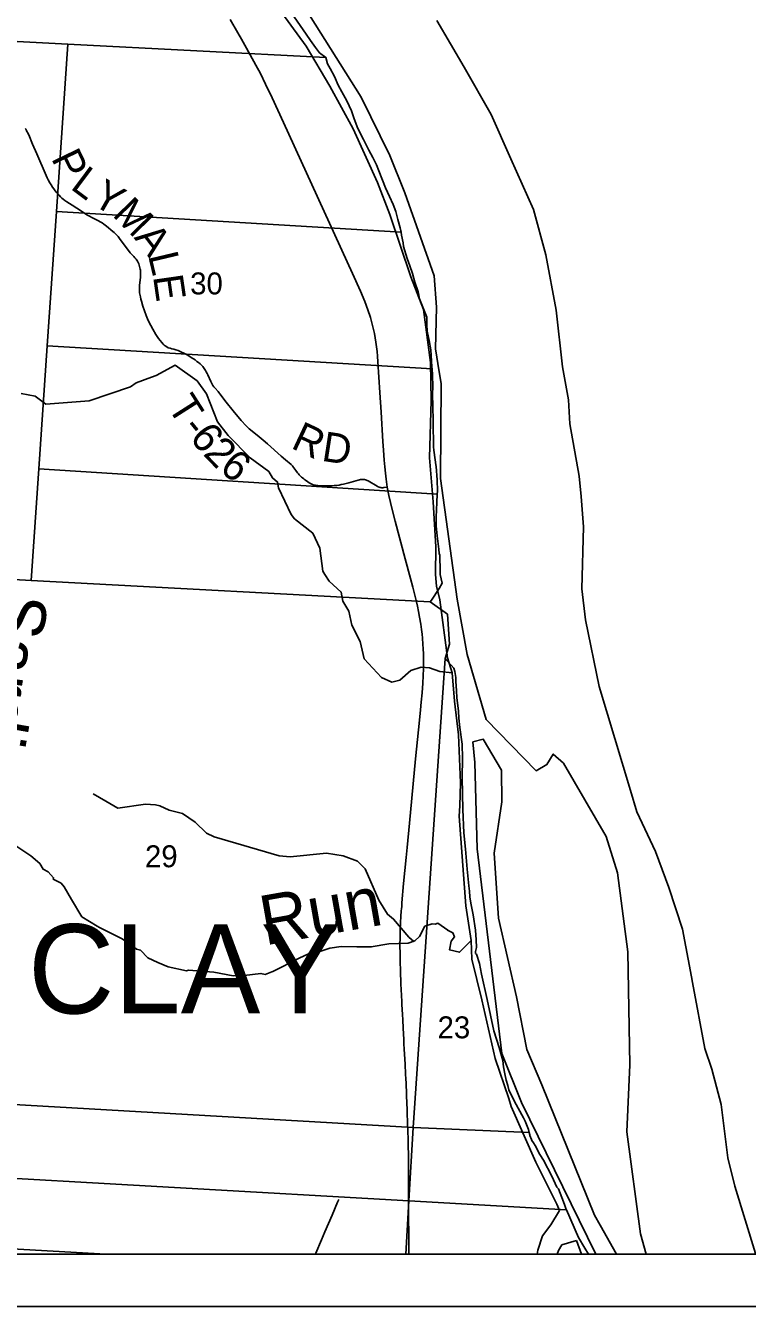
# Model space of a CAD drawing. Extents: x 21.4 to 65.3, y 4 to 26.
# Drawn here: x 27.53 to 28.907, y 17.954 to 20.4 of the extents above; entities that cross this region are included whole.
import ezdxf

# ---------------------------------------------------------------- set-up
doc = ezdxf.new("R2010")
doc.units = 0
for name, color, linetype in [('Default', 7, 'Continuous'), ('GM_X_Major_River', 7, 'Continuous'), ('GM_X_Minor_River', 7, 'Continuous'), ('GM_X_Minor_River_Text', 7, 'Continuous'), ('GM_X_Section', 7, 'Continuous'), ('GM_X_Section_Text', 7, 'Continuous'), ('GM_X_State_Route', 7, 'Continuous'), ('GM_X_Township_Road', 7, 'Continuous'), ('GM_X_Township_Road_Text', 7, 'Continuous'), ('GM_X_Township_Text', 7, 'Continuous'), ('SH_Cut_Line', 7, 'Continuous'), ('SH_Data', 7, 'Continuous')]:
    doc.layers.add(name, color=color, linetype=linetype)

msp = doc.modelspace()

# ---------------------------------------------------------------- linework, layer by layer
at = {"layer": 'Default'}
msp.add_lwpolyline([(25.1151, 18.0542), (28.6177, 18.0542), (28.4756, 18.3435), (28.4382, 18.4371), (28.3913, 18.8283), (28.3871, 18.9932), (28.383, 19.0322), (28.403, 19.0375), (28.4378, 18.9784), (28.4382, 18.9181), (28.4238, 18.8196), (28.4321, 18.6956), (28.4665, 18.5455), (28.4862, 18.4451), (28.5145, 18.3773), (28.615, 18.1282), (28.626, 18.1093), (28.6572, 18.0542), (28.7135, 18.0542), (28.7031, 18.0926), (28.6766, 18.2878), (28.6823, 18.4156), (28.6789, 18.6316), (28.6593, 18.7821), (28.6373, 18.8514), (28.5557, 18.992), (28.5364, 19.0091), (28.5243, 18.989), (28.5036, 18.9773), (28.4087, 19.075), (28.372, 19.1994), (28.3531, 19.3047), (28.3214, 19.5352), (28.3225, 19.7171), (28.3188, 19.7391), (28.312, 19.7834), (28.3135, 19.8626), (28.309, 19.9226), (28.2534, 20.0809), (28.2243, 20.1526), (28.1702, 20.2638), (28.0527, 20.4505)], dxfattribs=at)
for points in [[(27.6828, 18.0542), (28.255, 18.0542), (28.2609, 18.1555), (27.3661, 18.2064), (27.3583, 18.0722)], [(28.255, 18.0542), (28.6038, 18.0542), (28.5966, 18.0656), (28.5848, 18.0857), (28.562, 18.1384), (28.2609, 18.1555)], [(27.3572, 18.0542), (27.6828, 18.0542), (27.3583, 18.0722)]]:
    msp.add_lwpolyline(points, close=True, dxfattribs=at)
at = {"layer": 'GM_X_Major_River'}
msp.add_line((28.5806, 18.0797), (28.5903, 18.0542), dxfattribs=at)
for points in [[(27.9894, 20.4659), (28.0651, 20.3615), (28.1104, 20.2846), (28.1549, 20.2032), (28.2011, 20.1005), (28.2244, 20.0398), (28.2645, 19.9206), (28.2888, 19.8579)], [(28.5418, 19.8568), (28.5222, 19.9629), (28.4988, 20.0493), (28.4553, 20.1463), (28.4179, 20.2304), (28.3665, 20.3213), (28.3144, 20.4103)], [(28.2888, 19.8579), (28.3022, 19.7567), (28.3034, 19.6842), (28.3002, 19.5746), (28.3071, 19.4908), (28.3124, 19.4047), (28.312, 19.352), (28.3136, 19.33), (28.3198, 19.3038), (28.3344, 19.1931), (28.3436, 19.164), (28.3477, 19.1101), (28.3556, 19.0461), (28.3595, 18.9543), (28.3579, 18.9099), (28.3572, 18.8902), (28.3699, 18.7195), (28.3801, 18.6528), (28.3814, 18.6175), (28.4003, 18.5395), (28.4259, 18.4278), (28.4517, 18.3513), (28.4559, 18.3357), (28.5034, 18.2298), (28.5435, 18.1496), (28.5485, 18.1375)], [(28.9229, 18.0542), (28.9225, 18.0552), (28.8829, 18.1839), (28.8697, 18.2381), (28.8567, 18.3397), (28.8393, 18.4071), (28.8255, 18.4465), (28.8025, 18.5727), (28.8002, 18.5833), (28.7834, 18.6746), (28.7573, 18.7545), (28.7316, 18.823), (28.696, 18.899), (28.6837, 18.9396), (28.624, 19.1384), (28.5983, 19.2653), (28.5912, 19.3244), (28.594, 19.4432), (28.5899, 19.5008), (28.5859, 19.5399), (28.5683, 19.6396), (28.5654, 19.6858), (28.5541, 19.7487), (28.5418, 19.8568)], [(28.5485, 18.1375), (28.532, 18.1097), (28.5159, 18.0888), (28.5073, 18.0618), (28.5058, 18.0542)], [(28.5439, 18.0542), (28.5463, 18.0609), (28.553, 18.0715), (28.5806, 18.0797)]]:
    msp.add_lwpolyline(points, dxfattribs=at)
at = {"layer": 'GM_X_Minor_River'}
for points in [[(28.3436, 19.164), (28.3203, 19.1666), (28.3001, 19.1741), (28.2847, 19.175), (28.2648, 19.1688), (28.2435, 19.1501), (28.2286, 19.1467), (28.2085, 19.1554), (28.1756, 19.191), (28.1679, 19.2239), (28.1522, 19.2555), (28.1462, 19.2819), (28.135, 19.3009), (28.1318, 19.3184), (28.1086, 19.3393), (28.1007, 19.3521), (28.0967, 19.3583), (28.0913, 19.4025), (28.0777, 19.4307), (28.0427, 19.4587), (28.0365, 19.4669), (28.0123, 19.5174), (28.0104, 19.5285), (28.0008, 19.5364), (27.9936, 19.5488), (27.9581, 19.575), (27.916, 19.6177), (27.8956, 19.6438), (27.8749, 19.6969), (27.8568, 19.7221), (27.8149, 19.7516), (27.7785, 19.7322), (27.77, 19.7287), (27.7406, 19.7179), (27.7294, 19.7106), (27.6511, 19.6835), (27.5681, 19.6771), (27.5478, 19.6925), (27.5211, 19.6979)], [(28.2701, 18.6514), (28.2607, 18.6596), (28.2319, 18.694), (28.2201, 18.7031), (28.2039, 18.7302), (28.1774, 18.7899), (28.1631, 18.8048), (28.1358, 18.8148), (28.1038, 18.8196), (28.0341, 18.8131), (28.0137, 18.8145), (27.8893, 18.8511), (27.8748, 18.858), (27.8531, 18.8788), (27.8291, 18.8956), (27.8032, 18.9021), (27.7857, 18.9099), (27.7774, 18.912), (27.7582, 18.9134), (27.7054, 18.906), (27.6824, 18.9189), (27.6586, 18.9333)], [(28.2942, 18.6811), (28.2911, 18.6801), (28.2809, 18.6607), (28.2722, 18.6523), (28.2594, 18.6481), (28.2227, 18.6469), (28.1891, 18.6407), (28.1619, 18.641), (28.132, 18.6417), (28.1101, 18.6386), (28.0731, 18.6264), (28.0697, 18.6275), (28.0515, 18.6195), (28.0016, 18.5939), (27.9994, 18.5931), (27.9865, 18.5881), (27.9786, 18.59), (27.9465, 18.5861), (27.9257, 18.5857), (27.8886, 18.5925), (27.8402, 18.5965), (27.8368, 18.595), (27.8017, 18.6025), (27.782, 18.6108), (27.7631, 18.6199), (27.7491, 18.6343), (27.7412, 18.6362), (27.7332, 18.6434), (27.7128, 18.6571), (27.6704, 18.6779), (27.6663, 18.6805), (27.6368, 18.6983), (27.6171, 18.7313), (27.6034, 18.7556), (27.5974, 18.7625), (27.5823, 18.7704), (27.583, 18.7727), (27.5724, 18.7841), (27.5633, 18.789), (27.5569, 18.8), (27.5395, 18.8144), (27.5092, 18.8348)], [(28.2933, 18.6808), (28.3051, 18.6846)], [(28.3351, 18.6727), (28.3164, 18.6862), (28.3108, 18.6839), (28.3051, 18.6846)], [(28.3801, 18.6528), (28.3577, 18.6305), (28.3384, 18.6353), (28.3414, 18.6517), (28.3478, 18.6597), (28.3448, 18.6677), (28.3349, 18.6728)]]:
    msp.add_lwpolyline(points, dxfattribs=at)
at = {"layer": 'GM_X_Section'}
for points in [[(27.3731, 20.4834), (28.0222, 20.4469), (28.0334, 20.4311), (28.0422, 20.4171), (28.0647, 20.3839), (28.073, 20.3722), (28.0829, 20.3589), (28.0906, 20.3484), (28.1023, 20.3397), (27.6101, 20.3651), (27.367, 20.3777)], [(27.367, 20.3777), (27.6101, 20.3651), (27.5883, 20.0453), (27.5709, 19.7889), (27.5549, 19.5538), (27.5403, 19.3404), (27.3079, 19.3538), (27.3231, 19.6175), (27.3378, 19.8728), (27.3527, 20.1302)], [(27.6101, 20.3651), (28.1023, 20.3397), (28.1058, 20.3272), (28.1107, 20.3185), (28.1187, 20.303), (28.126, 20.2867), (28.1333, 20.2742), (28.1424, 20.2568), (28.1512, 20.2376), (28.1565, 20.2224), (28.1638, 20.2039), (28.1741, 20.1831), (28.1848, 20.1627), (28.1924, 20.1487), (28.1993, 20.1347), (28.2035, 20.1233), (28.2161, 20.0908), (28.2237, 20.0741), (28.231, 20.0586), (28.236, 20.0454), (28.2398, 20.0302), (28.2444, 20.014), (28.246, 20.0061), (27.5883, 20.0453)], [(28.246, 20.0061), (28.2471, 20.0003), (28.2502, 19.9856), (28.251, 19.9784), (28.2575, 19.9557), (28.2625, 19.9417), (28.2678, 19.9269), (28.272, 19.9106), (28.2789, 19.8921), (28.2813, 19.8788), (28.2949, 19.8438), (28.2953, 19.8283), (28.2961, 19.8173), (28.2965, 19.8139), (28.2999, 19.7991), (28.303, 19.7814), (28.305, 19.7484), (28.3052, 19.7447), (27.5709, 19.7889), (27.5883, 20.0453)], [(27.5709, 19.7889), (28.3052, 19.7447), (28.3059, 19.7329), (28.3067, 19.7109), (28.306, 19.6957), (28.306, 19.6885), (28.3064, 19.6821), (28.3073, 19.6374), (28.3078, 19.6018), (28.3079, 19.5957), (28.3086, 19.5893), (28.311, 19.5711), (28.3125, 19.5613), (28.3133, 19.5582), (28.3149, 19.5328), (28.3153, 19.5112), (28.3151, 19.5052), (27.5549, 19.5538)], [(28.3151, 19.5052), (28.3143, 19.4893), (28.3129, 19.4616), (28.3129, 19.4453), (28.3149, 19.4256), (28.318, 19.4006), (28.3188, 19.3919), (28.3199, 19.3893), (28.3208, 19.3578), (28.3208, 19.3521), (28.3247, 19.3355), (28.3186, 19.3256), (28.3039, 19.3032), (28.3017, 19.2998), (27.5403, 19.3404), (27.5549, 19.5538)], [(27.5403, 19.3404), (28.3017, 19.2998), (28.3345, 19.2762), (28.3347, 19.276), (28.3387, 19.2192), (28.3305, 19.1915), (28.269, 18.2956), (27.3744, 18.3474), (27.2401, 18.3567), (27.2592, 18.6074), (27.2763, 18.86), (27.2925, 19.1065), (27.3079, 19.3538)], [(28.269, 18.2956), (28.3305, 19.1915), (28.3465, 19.173), (28.3484, 19.1666), (28.3491, 19.1628), (28.3507, 19.1552), (28.3503, 19.148), (28.3519, 19.1306), (28.3527, 19.1166), (28.3539, 19.1071), (28.3555, 19.0912), (28.3563, 19.0779), (28.3582, 19.0601), (28.3625, 19.0279), (28.363, 19.0014), (28.3627, 18.9639), (28.3637, 18.9033), (28.3661, 18.8586), (28.3693, 18.8275), (28.3724, 18.7893), (28.3756, 18.7575), (28.3764, 18.7472), (28.3772, 18.7362), (28.3791, 18.7245), (28.3834, 18.7018), (28.388, 18.6726), (28.3896, 18.6545), (28.39, 18.6397), (28.3878, 18.6321), (28.3878, 18.6306), (28.3882, 18.6283), (28.3897, 18.6268), (28.3954, 18.609), (28.3997, 18.5886), (28.4104, 18.5405), (28.4231, 18.4807), (28.4331, 18.4485), (28.4377, 18.4326), (28.44, 18.4235), (28.4416, 18.4114), (28.4439, 18.3985), (28.4466, 18.3864), (28.4497, 18.3758), (28.452, 18.3675), (28.4619, 18.3467), (28.4695, 18.3327), (28.4794, 18.3141), (28.4829, 18.3077), (28.4894, 18.2922), (28.4908, 18.2861)], [(27.3744, 18.3474), (28.269, 18.2956), (28.2609, 18.1555), (27.3661, 18.2064)], [(28.269, 18.2956), (28.4908, 18.2861), (28.4917, 18.282), (28.492, 18.2805), (28.4947, 18.2729), (28.4957, 18.2713), (28.4985, 18.2668), (28.502, 18.2612), (28.5111, 18.2445), (28.518, 18.2332), (28.5336, 18.2026), (28.5435, 18.1821), (28.5447, 18.1806), (28.5462, 18.1784), (28.5561, 18.1541), (28.5584, 18.1469), (28.5607, 18.1413), (28.562, 18.1384), (28.2609, 18.1555)]]:
    msp.add_lwpolyline(points, close=True, dxfattribs=at)
at = {"layer": 'GM_X_State_Route'}
msp.add_lwpolyline([(28.2611, 18.0542), (28.261, 18.0578), (28.2609, 18.0677), (28.2608, 18.0914), (28.2604, 18.1237), (28.2604, 18.152), (28.2603, 18.174), (28.2603, 18.2005), (28.26, 18.2298), (28.2596, 18.2746), (28.2592, 18.2876), (28.2578, 18.3235), (28.2574, 18.3335), (28.2572, 18.3394), (28.2556, 18.3807), (28.2552, 18.3885), (28.2547, 18.3974), (28.2536, 18.4166), (28.252, 18.4457), (28.2516, 18.4559), (28.2512, 18.4642), (28.25, 18.4853), (28.2492, 18.5014), (28.2486, 18.5119), (28.2476, 18.5306), (28.2474, 18.5368), (28.2463, 18.5591), (28.2458, 18.5696), (28.2447, 18.5957), (28.2443, 18.6125), (28.2442, 18.6182), (28.2441, 18.6237), (28.2441, 18.633), (28.244, 18.6379), (28.244, 18.6439), (28.244, 18.6479), (28.2441, 18.6547), (28.2441, 18.659), (28.2442, 18.6621), (28.2443, 18.6681), (28.2445, 18.6746), (28.2446, 18.6789), (28.2447, 18.6808), (28.2448, 18.6833), (28.2449, 18.6858), (28.2451, 18.6907), (28.2454, 18.6956), (28.2457, 18.7005), (28.2459, 18.7029), (28.2461, 18.706), (28.2465, 18.7101), (28.2467, 18.7131), (28.2473, 18.7188), (28.2478, 18.7248), (28.2508, 18.762), (28.2558, 18.8114), (28.2577, 18.8306), (28.262, 18.877), (28.2739, 19.0002), (28.2813, 19.0736), (28.283, 19.0934), (28.2846, 19.1082), (28.2863, 19.1262), (28.2876, 19.1447), (28.2882, 19.1582), (28.2888, 19.1726), (28.2889, 19.1887), (28.2887, 19.2005), (28.2882, 19.2098), (28.2877, 19.2191), (28.2868, 19.2306), (28.2862, 19.2382), (28.2851, 19.2471), (28.2838, 19.2573), (28.2814, 19.2705), (28.2795, 19.2811), (28.2773, 19.2914), (28.2749, 19.3023), (28.2717, 19.3152), (28.2687, 19.3276), (28.2642, 19.3443), (28.2541, 19.3823), (28.2345, 19.4542), (28.2282, 19.4789), (28.2258, 19.4896), (28.2227, 19.5032), (28.2197, 19.5189), (28.2175, 19.5339), (28.2161, 19.5453), (28.2148, 19.5577), (28.2138, 19.5707), (28.2125, 19.5896), (28.2115, 19.6059), (28.208, 19.6622), (28.2056, 19.7), (28.202, 19.7583), (28.2011, 19.769), (28.2003, 19.7781), (28.198, 19.7959), (28.1951, 19.8124), (28.1918, 19.8275), (28.1875, 19.8431), (28.1828, 19.8578), (28.1769, 19.8735), (28.1686, 19.8935), (28.1535, 19.9269), (28.0214, 20.2156), (27.9999, 20.2625), (27.9872, 20.2888), (27.9776, 20.3088), (27.9687, 20.3246), (27.951, 20.3575), (27.9415, 20.3744), (27.9346, 20.3867), (27.9197, 20.4118)], dxfattribs=at)
at = {"layer": 'GM_X_Township_Road'}
for points in [[(27.5285, 20.2041), (27.5297, 20.2024), (27.5311, 20.2002), (27.5322, 20.1982), (27.5335, 20.1958), (27.5345, 20.1938), (27.5355, 20.1916), (27.543, 20.1742), (27.551, 20.1558), (27.5688, 20.114), (27.5707, 20.11), (27.5729, 20.1056), (27.5759, 20.1002), (27.5782, 20.0962), (27.5809, 20.0918), (27.5832, 20.0887), (27.5861, 20.0849), (27.5894, 20.081), (27.5934, 20.0764), (27.5961, 20.0737), (27.5987, 20.0711), (27.6014, 20.0688), (27.6045, 20.0663), (27.6081, 20.0638), (27.6182, 20.0574), (27.6359, 20.0459), (27.6464, 20.0393), (27.6514, 20.0365), (27.6562, 20.0338), (27.6688, 20.0276), (27.6719, 20.0258), (27.6754, 20.0237), (27.6787, 20.0215), (27.6814, 20.0194), (27.6839, 20.0174), (27.6961, 20.0074), (27.6987, 20.0051), (27.7012, 20.0026), (27.7035, 20.0003), (27.7059, 19.9974), (27.7085, 19.9941), (27.729, 19.9666), (27.7342, 19.9611), (27.7362, 19.9592), (27.7383, 19.957), (27.7403, 19.9545), (27.7417, 19.9526), (27.7431, 19.9503), (27.7442, 19.9481), (27.7453, 19.9454), (27.7463, 19.9426), (27.747, 19.9402), (27.7477, 19.9378), (27.7481, 19.9354), (27.7485, 19.9332), (27.7487, 19.9306), (27.7489, 19.9282), (27.7489, 19.9257), (27.7489, 19.9229), (27.7486, 19.9195), (27.7469, 19.9045), (27.7467, 19.9022), (27.7467, 19.8996), (27.7467, 19.8972), (27.7468, 19.8951), (27.7469, 19.8929), (27.7472, 19.8901), (27.7475, 19.8875), (27.748, 19.8848), (27.7485, 19.8821), (27.7496, 19.878), (27.7506, 19.874), (27.7533, 19.8648), (27.7593, 19.847), (27.7621, 19.8403), (27.7652, 19.8333), (27.7683, 19.8275), (27.7722, 19.8205), (27.7779, 19.8105), (27.7805, 19.8066), (27.7831, 19.803), (27.7861, 19.7991), (27.7896, 19.7949), (27.7923, 19.7918), (27.7941, 19.7901), (27.796, 19.7886), (27.7988, 19.7867), (27.8016, 19.7852), (27.8051, 19.7841), (27.8084, 19.7832), (27.8124, 19.7823), (27.8163, 19.7811), (27.8208, 19.7797), (27.826, 19.7776), (27.8326, 19.7744), (27.8391, 19.7707), (27.8453, 19.7668), (27.8529, 19.7618), (27.8565, 19.7591), (27.8596, 19.7567), (27.8625, 19.7544), (27.8648, 19.7523), (27.8665, 19.7507), (27.8679, 19.7491), (27.8692, 19.7476), (27.8704, 19.7458), (27.8716, 19.7439), (27.8728, 19.7418), (27.8742, 19.7393), (27.8758, 19.7362), (27.8772, 19.7333), (27.8831, 19.7205), (27.885, 19.7169), (27.8871, 19.7133), (27.889, 19.7107), (27.8914, 19.7079), (27.8969, 19.7018), (27.8986, 19.6995), (27.9004, 19.6971), (27.9124, 19.6814), (27.9258, 19.6646), (27.941, 19.6461), (27.9504, 19.6362), (27.9531, 19.6335), (27.956, 19.6306), (27.9589, 19.6281), (27.9627, 19.625), (27.9712, 19.6185), (27.983, 19.6085), (27.991, 19.6014), (28.0171, 19.5778), (28.0253, 19.571), (28.036, 19.562), (28.0373, 19.5611), (28.0381, 19.5604), (28.0388, 19.5596), (28.0398, 19.5583), (28.0452, 19.5505), (28.0487, 19.546), (28.0502, 19.5442), (28.0518, 19.5424), (28.0538, 19.5403), (28.056, 19.5382), (28.058, 19.5364), (28.0602, 19.5346), (28.0624, 19.533), (28.0654, 19.5309), (28.0684, 19.5289), (28.0709, 19.5272), (28.0733, 19.5257), (28.0755, 19.5245), (28.0773, 19.5237), (28.0795, 19.5229), (28.0819, 19.5224), (28.0843, 19.5221), (28.0872, 19.5218), (28.0907, 19.5216), (28.0944, 19.5214), (28.0984, 19.5212), (28.113, 19.5215), (28.1185, 19.5219), (28.1233, 19.5223), (28.1277, 19.523), (28.132, 19.5237), (28.1364, 19.5246), (28.1411, 19.5257), (28.1463, 19.527), (28.164, 19.5322), (28.1666, 19.5328), (28.1685, 19.5332), (28.1704, 19.5335), (28.1723, 19.5336), (28.1742, 19.5336), (28.1762, 19.5334), (28.1783, 19.5329), (28.1799, 19.5323), (28.1814, 19.5317), (28.183, 19.5309), (28.2006, 19.5207), (28.2024, 19.5198), (28.2041, 19.519), (28.2059, 19.5184), (28.2075, 19.5181), (28.2092, 19.5179), (28.2111, 19.5178), (28.2133, 19.518), (28.2197, 19.5189)], [(28.1272, 18.1581), (28.125, 18.153), (28.1144, 18.1281), (28.1005, 18.0966), (28.094, 18.0812), (28.0832, 18.0556), (28.0826, 18.0542)]]:
    msp.add_lwpolyline(points, dxfattribs=at)
at = {"layer": 'SH_Cut_Line'}
msp.add_lwpolyline([(23.5473, 18.0542), (28.6177, 18.0542), (28.4756, 18.3435), (28.4382, 18.4371), (28.3913, 18.8283), (28.3871, 18.9932), (28.383, 19.0322), (28.403, 19.0375), (28.4378, 18.9784), (28.4382, 18.9181), (28.4238, 18.8196), (28.4321, 18.6956), (28.4665, 18.5455), (28.4862, 18.4451), (28.5145, 18.3773), (28.615, 18.1282), (28.626, 18.1093), (28.6572, 18.0542), (28.7135, 18.0542), (28.7031, 18.0926), (28.6766, 18.2878), (28.6823, 18.4156), (28.6789, 18.6316), (28.6593, 18.7821), (28.6373, 18.8514), (28.5557, 18.992), (28.5364, 19.0091), (28.5243, 18.989), (28.5036, 18.9773), (28.4087, 19.075), (28.372, 19.1994), (28.3531, 19.3047), (28.3214, 19.5352), (28.3225, 19.7171), (28.3188, 19.7391), (28.312, 19.7834), (28.3135, 19.8626), (28.309, 19.9226), (28.2534, 20.0809), (28.2243, 20.1526), (28.1702, 20.2638), (28.0527, 20.4505)], dxfattribs=at)
at = {"layer": 'SH_Data'}
for p, q in [((23.5473, 18.0542), (30.3473, 18.0542)), ((23.4473, 17.9542), (30.4473, 17.9542))]:
    msp.add_line(p, q, dxfattribs=at)

# ---------------------------------------------------------------- texts
at = {"layer": 'GM_X_Minor_River_Text'}
for s, height, rotation, p in [('Sardis', 0.0947, 259.9987, (27.4813, 19.3234)), ('Run', 0.09469, 10.0015, (27.9859, 18.6433))]:
    msp.add_text(s, height=height, rotation=rotation, dxfattribs=at).set_placement(p)
at = {"layer": 'GM_X_Section_Text'}
for s, p in [('30', (27.8436, 19.8871)), ('29', (27.7574, 18.7929)), ('23', (28.3157, 18.4662))]:
    msp.add_text(s, height=0.04186, rotation=0, dxfattribs=at).set_placement(p)
at = {"layer": 'GM_X_Township_Road_Text'}
for s, rotation, p in [('P', 295.7406, (27.5777, 20.1472)), ('L', 323.2377, (27.6131, 20.09)), ('Y', 330.0747, (27.6533, 20.0605)), ('M', 314.386, (27.6934, 20.038)), ('A', 307.4309, (27.7353, 19.9953)), ('L', 283.3986, (27.7631, 19.9613)), ('E', 278.2483, (27.7726, 19.9213)), ('T', 302.5192, (27.7991, 19.6727)), ('-', 309.2461, (27.8262, 19.6309)), ('6', 308.9817, (27.841, 19.6129)), ('R', 334.8856, (28.0339, 19.5944)), ('D', 351.2587, (28.0928, 19.5695)), ('2', 314.3218, (27.8668, 19.5814)), ('6', 321.8031, (27.8973, 19.551))]:
    msp.add_text(s, height=0.0568, rotation=rotation, dxfattribs=at).set_placement(p)
at = {"layer": 'GM_X_Township_Text'}
msp.add_text('CLAY', height=0.17045, rotation=0, dxfattribs=at).set_placement((27.5342, 18.5136))

doc.saveas('drawing.dxf')
